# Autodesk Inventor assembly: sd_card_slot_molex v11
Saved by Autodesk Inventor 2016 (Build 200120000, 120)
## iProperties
Created: 2018-05
Part Number: sd_card_slot_molex v11
Document SubType Name: Assembly
Designer: Administrator
Title: sd_card_slot_molex v11
Author: Administrator
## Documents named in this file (4)
- c:\worker\convert-fusion-mar-2018\tmp\job-1\16\output\files\8c58ff39-88bb-4352-afd9-60265520bae5\sd_card_slot_molex v11.iam
- c:\worker\convert-fusion-mar-2018\tmp\job-1\16\output\files\8c58ff39-88bb-4352-afd9-60265520bae5\housing.iam
- c:\worker\convert-fusion-mar-2018\tmp\job-1\16\output\files\8c58ff39-88bb-4352-afd9-60265520bae5\base.ipt
- c:\worker\convert-fusion-mar-2018\tmp\job-1\16\output\files\8c58ff39-88bb-4352-afd9-60265520bae5\leads.iam
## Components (3 placed, 3 different names)
1. housing:1 [sub-assembly]
2. base:1
3. leads:1 [sub-assembly]
